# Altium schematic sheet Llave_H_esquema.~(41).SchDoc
size A4
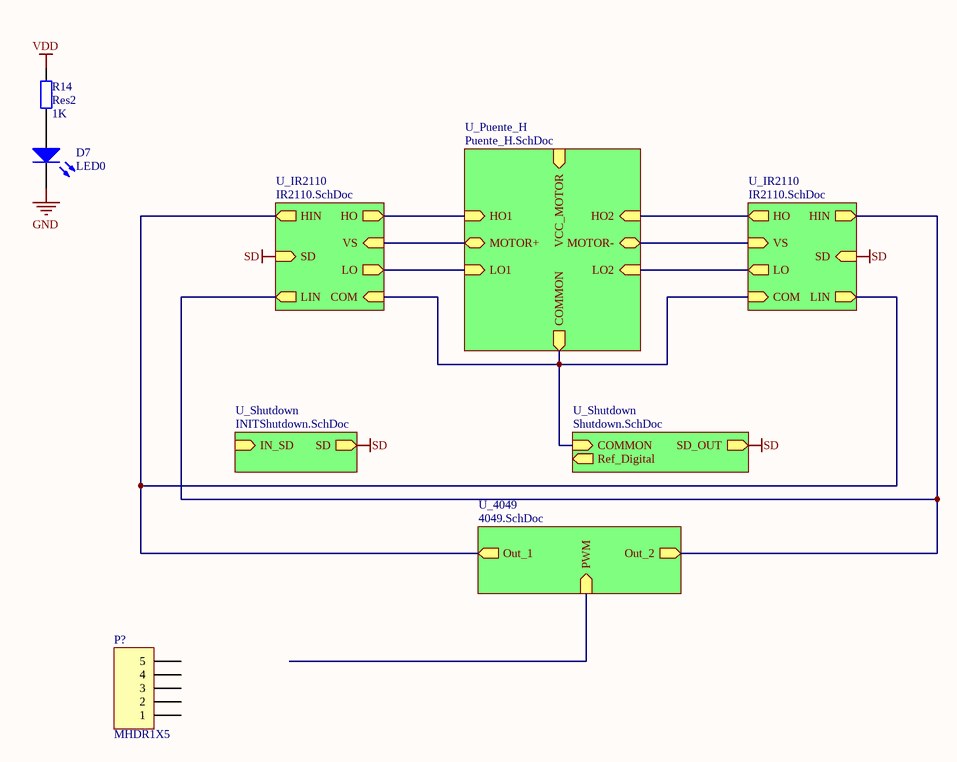
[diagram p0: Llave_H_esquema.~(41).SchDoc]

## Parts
D7  LED0  [LED-0]
P?  MHDR1X5  [MHDR1X5]
R14  Res2  value 1K  [AXIAL-0.4]

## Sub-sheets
U_4049 = 4049.SchDoc: PWM (in), Out_1 (out), Out_2 (out)
U_IR2110 = IR2110.SchDoc: SD (in), HIN (out), LIN (out), HO (out), LO (out), VS (in), COM (in)
U_IR2110 = IR2110.SchDoc: SD (in), HIN (out), LIN (out), HO (out), LO (out), VS (in), COM (in)
U_Puente_H = Puente_H.SchDoc: HO1 (in), LO1 (in), HO2 (in), LO2 (in), MOTOR+ (bidir), MOTOR- (bidir), VCC_MOTOR (in), COMMON (out)
U_Shutdown = INITShutdown.SchDoc: IN_SD (in), SD (out)
U_Shutdown = Shutdown.SchDoc: COMMON (in), SD_OUT (out), Ref_Digital (out)

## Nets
GND: D7.2(K)
SD: sheet U_IR2110/SD, sheet U_IR2110/SD, sheet U_Shutdown/SD, sheet U_Shutdown/SD_OUT
VDD: R14.2
NetD7_1: D7.1(A) R14.1
(unnamed): sheet U_IR2110/HIN, sheet U_IR2110/LIN, sheet U_4049/Out_1
(unnamed): sheet U_IR2110/LIN, sheet U_IR2110/HIN, sheet U_4049/Out_2  [a separate net that carries the same name]
(unnamed): sheet U_IR2110/HO, sheet U_Puente_H/HO1  [a separate net that carries the same name]
(unnamed): sheet U_IR2110/LO, sheet U_Puente_H/LO1  [a separate net that carries the same name]
(unnamed): sheet U_IR2110/VS, sheet U_Puente_H/MOTOR+  [a separate net that carries the same name]
(unnamed): sheet U_IR2110/COM, sheet U_IR2110/COM, sheet U_Puente_H/COMMON, sheet U_Shutdown/COMMON  [a separate net that carries the same name]
(unnamed): sheet U_IR2110/HO, sheet U_Puente_H/HO2  [a separate net that carries the same name]
(unnamed): sheet U_IR2110/LO, sheet U_Puente_H/LO2  [a separate net that carries the same name]
(unnamed): sheet U_IR2110/VS, sheet U_Puente_H/MOTOR-  [a separate net that carries the same name]

Not connected (* = marked no-connect by the designer): P? 1 2 3 4 5

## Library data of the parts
D7 = LED0: Typical INFRARED GaAs LED
P? = MHDR1X5: Header, 5-Pin
R14 = Res2: Resistor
